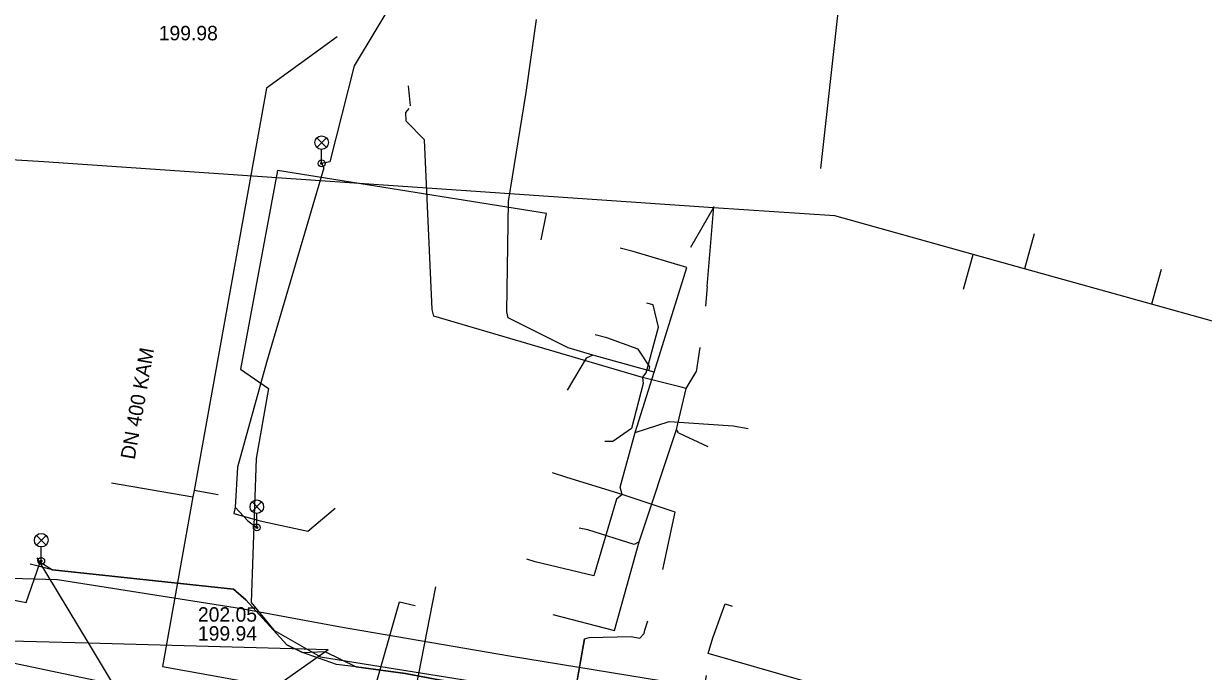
# Model space of a CAD drawing. Extents: x -596228 to -595156, y -1161235 to -1159373.
# Drawn here: x -596092 to -596026.7, y -1160278.1 to -1160242.3 of the extents above; entities that cross this region are included whole.
import ezdxf

# ---------------------------------------------------------------- set-up
doc = ezdxf.new("R2010")
doc.units = 0
for name, color, linetype in [('Vrstva 1', 7, 'Continuous'), ('Vrstva 12', 7, 'Continuous'), ('Vrstva 14', 7, 'Continuous'), ('Vrstva 16', 7, 'Continuous'), ('Vrstva 33', 7, 'Continuous'), ('Vrstva 4', 7, 'Continuous'), ('Vrstva 42', 7, 'Continuous'), ('Vrstva 5', 7, 'Continuous'), ('Vrstva 54', 7, 'Continuous'), ('Vrstva 55', 7, 'Continuous'), ('Vrstva 58', 7, 'Continuous'), ('Vrstva 9', 7, 'Continuous')]:
    doc.layers.add(name, color=color, linetype=linetype)

msp = doc.modelspace()

# ---------------------------------------------------------------- linework, layer by layer
at = {"layer": 'Vrstva 1'}
for p, q in [((-596046.34, -1160236.52), (-596047.88, -1160250.29)), ((-596074.64, -1160242.99), (-596078.56, -1160245.83)), ((-596070.71, -1160245.714), (-596070.6, -1160246.818)), ((-596069.388, -1160258.092), (-596069.806, -1160248.695)), ((-596055.054, -1160254.641), (-596053.794, -1160252.452)), ((-596054.16, -1160256.817), (-596053.787, -1160252.381)), ((-596036.053, -1160253.906), (-596036.589, -1160255.833)), ((-596039.967, -1160256.969), (-596039.431, -1160255.042)), ((-596029.011, -1160255.866), (-596029.547, -1160257.793)), ((-596054.16, -1160256.817), (-596054.245, -1160257.908)), ((-596069.278, -1160258.457), (-596069.388, -1160258.092)), ((-596057.143, -1160257.832), (-596057.484, -1160257.727)), ((-596056.838, -1160259.06), (-596057.143, -1160257.832)), ((-596057.527, -1160261.586), (-596056.838, -1160259.06)), ((-596054.564, -1160260.189), (-596054.765, -1160261.538)), ((-596057.725, -1160261.857), (-596057.527, -1160261.586)), ((-596055.31, -1160262.464), (-596054.765, -1160261.538)), ((-596055.853, -1160264.726), (-596055.31, -1160262.464)), ((-596055.31, -1160262.464), (-596055.59, -1160262.38)), ((-596058.349, -1160264.68), (-596059.382, -1160265.384)), ((-596057.912, -1160270.944), (-596055.853, -1160264.726)), ((-596055.747, -1160264.913), (-596055.853, -1160264.726)), ((-596059.382, -1160265.384), (-596059.827, -1160265.383)), ((-596055.747, -1160264.913), (-596054.118, -1160265.676)), ((-596087.13, -1160267.67), (-596082.629, -1160268.456)), ((-596081.22, -1160268.34), (-596082.566, -1160268.104))]:
    msp.add_line(p, q, dxfattribs=at)
for points in [[(-596078.56, -1160245.83), (-596082.566, -1160268.104), (-596082.629, -1160268.456), (-596084.32, -1160277.84)], [(-596069.806, -1160248.695), (-596070.817, -1160247.656), (-596070.835, -1160247.186), (-596070.655, -1160246.965)], [(-596090.88, -1160249.92), (-596130.326, -1160247.508), (-596132.717, -1160247.548), (-596135.072, -1160247.752)], [(-596047.09, -1160252.91), (-596053.794, -1160252.452), (-596090.88, -1160249.92)], [(-595998.91, -1160266.32), (-596008.526, -1160263.644), (-596008.747, -1160263.582), (-596020.751, -1160260.241), (-596029.547, -1160257.793), (-596036.589, -1160255.833), (-596039.431, -1160255.042), (-596047.09, -1160252.91)], [(-596055.59, -1160262.38), (-596057.725, -1160261.857), (-596069.278, -1160258.457)], [(-596057.725, -1160261.857), (-596057.694, -1160262.181), (-596058.349, -1160264.68)], [(-596062.702, -1160274.964), (-596059.291, -1160275.843), (-596057.912, -1160270.944), (-596058.189, -1160271.083), (-596060.762, -1160270.288), (-596061.249, -1160270.195)]]:
    msp.add_lwpolyline(points, dxfattribs=at)
at = {"layer": 'Vrstva 12'}
msp.add_line((-596053.16, -1160274.38), (-596052.77, -1160274.5), dxfattribs=at)
for points in [[(-596063.35, -1160254.23), (-596063.05, -1160252.78), (-596077.95, -1160250.4), (-596080, -1160261.38), (-596078.44, -1160262.45), (-596079.12, -1160266.34)], [(-596079.12, -1160266.34), (-596079.4, -1160274.31), (-596078.14, -1160275.84), (-596075.57, -1160277.3), (-596050.88, -1160281.26)], [(-596040.07, -1160283.09), (-596040.34, -1160282.25), (-596042.34, -1160281.47), (-596048.05, -1160278.86), (-596048.83, -1160278.64), (-596054.1, -1160277.12), (-596053.84, -1160276.26), (-596053.16, -1160274.38)]]:
    msp.add_lwpolyline(points, dxfattribs=at)
at = {"layer": 'Vrstva 14'}
for points in [[(-596073.176, -1160281.516), (-596073.112, -1160281.148), (-596073.04, -1160280.732), (-596071.197, -1160274.261), (-596070.32, -1160274.463)], [(-596080.37, -1160280.262), (-596080.665, -1160280.21), (-596082.606, -1160279.77), (-596095.596, -1160277.035), (-596097.65, -1160276.599), (-596104.647, -1160275.11), (-596105.055, -1160275.03), (-596105.65, -1160274.913)]]:
    msp.add_lwpolyline(points, dxfattribs=at)
at = {"layer": 'Vrstva 16'}
msp.add_lwpolyline([(-596073.52, -1160295.83), (-596073.39, -1160294.96), (-596069.19, -1160273.53), (-596069.17, -1160273.44)], dxfattribs=at)
at = {"layer": 'Vrstva 33'}
for p, q in [((-596075.765, -1160248.585), (-596075.235, -1160249.115)), ((-596075.765, -1160249.115), (-596075.235, -1160248.585)), ((-596075.5, -1160250), (-596075.5, -1160249.225)), ((-596079.355, -1160268.735), (-596078.825, -1160269.265)), ((-596079.355, -1160269.265), (-596078.825, -1160268.735)), ((-596079.09, -1160270.15), (-596079.09, -1160269.375)), ((-596091.291, -1160270.589), (-596090.761, -1160271.119)), ((-596091.291, -1160271.119), (-596090.761, -1160270.589)), ((-596091.026, -1160272.004), (-596091.026, -1160271.229))]:
    msp.add_line(p, q, dxfattribs=at)
for centre, radius in [((-596075.5, -1160248.85), 0.375), ((-596075.5, -1160250), 0.19), ((-596075.5, -1160250), 0.05), ((-596079.09, -1160269), 0.375), ((-596079.09, -1160270.15), 0.19), ((-596091.026, -1160270.854), 0.375), ((-596079.09, -1160270.15), 0.05), ((-596091.026, -1160272.004), 0.19), ((-596091.026, -1160272.004), 0.05)]:
    msp.add_circle(centre, radius, dxfattribs=at)
at = {"layer": 'Vrstva 42'}
msp.add_lwpolyline([(-596138.863, -1160251.371), (-596138.543, -1160251.731), (-596138.529, -1160252.118), (-596138.95, -1160254.63), (-596139.9, -1160258.88), (-596140.56, -1160262.64), (-596140.86, -1160263.55), (-596140.76, -1160264.3), (-596140.55, -1160264.76), (-596139.94, -1160265.17), (-596135.36, -1160266.41), (-596127.49, -1160267.65), (-596118.72, -1160268.94), (-596109.14, -1160270.6), (-596103.64, -1160272.23), (-596095.93, -1160272.87), (-596090.12, -1160273.02), (-596079.94, -1160274.63), (-596074.46, -1160275.64), (-596065.09, -1160277.26), (-596056.63, -1160278.63), (-596054.34, -1160279.2), (-596054.18, -1160278.35)], dxfattribs=at)
at = {"layer": 'Vrstva 5'}
for p, q in [((-596064.183, -1160246.083), (-596063.596, -1160242.034)), ((-596065.155, -1160252.104), (-596064.183, -1160246.083)), ((-596065.248, -1160258.209), (-596065.155, -1160252.104)), ((-596065.175, -1160258.556), (-596065.248, -1160258.209)), ((-596059.704, -1160259.651), (-596060.345, -1160259.491)), ((-596057.97, -1160260.272), (-596059.704, -1160259.651)), ((-596060.845, -1160260.787), (-596061.905, -1160262.549)), ((-596060.489, -1160260.606), (-596060.845, -1160260.787)), ((-596057.083, -1160261.559), (-596060.489, -1160260.606)), ((-596057.329, -1160261.252), (-596057.97, -1160260.272)), ((-596057.377, -1160261.477), (-596057.329, -1160261.252)), ((-596058.141, -1160264.895), (-596057.083, -1160261.559)), ((-596052.709, -1160264.522), (-596051.89, -1160264.676)), ((-596058.969, -1160267.924), (-596058.141, -1160264.895)), ((-596061.929, -1160267.377), (-596062.724, -1160267.129)), ((-596058.857, -1160268.325), (-596061.929, -1160267.377)), ((-596058.857, -1160268.325), (-596058.969, -1160267.924)), ((-596059.167, -1160268.581), (-596060.433, -1160272.827)), ((-596058.857, -1160268.325), (-596059.167, -1160268.581)), ((-596055.927, -1160269.298), (-596058.857, -1160268.325)), ((-596056.616, -1160272.475), (-596055.927, -1160269.298)), ((-596063.673, -1160272.055), (-596064.134, -1160271.896)), ((-596060.433, -1160272.827), (-596063.673, -1160272.055)), ((-596057.647, -1160276.023), (-596057.612, -1160275.834)), ((-596057.612, -1160275.834), (-596057.435, -1160275.309)), ((-596061.927, -1160281.895), (-596060.95, -1160276.32)), ((-596060.95, -1160276.32), (-596060.689, -1160276.232)), ((-596057.873, -1160276.282), (-596057.647, -1160276.023))]:
    msp.add_line(p, q, dxfattribs=at)
for points in [[(-596057.083, -1160261.559), (-596055.281, -1160255.755), (-596058.246, -1160254.881), (-596058.965, -1160254.687)], [(-596060.489, -1160260.606), (-596061.85, -1160260.21), (-596065.175, -1160258.556)], [(-596058.141, -1160264.895), (-596056.256, -1160264.292), (-596052.709, -1160264.522)], [(-596060.689, -1160276.232), (-596058.367, -1160276.191), (-596057.873, -1160276.282)]]:
    msp.add_lwpolyline(points, dxfattribs=at)
at = {"layer": 'Vrstva 54'}
for p, q in [((-596091.27, -1160271.82), (-596088.43, -1160276.54)), ((-596107.59, -1160276.02), (-596088.43, -1160276.54)), ((-596088.43, -1160276.54), (-596075.14, -1160276.9)), ((-596088.43, -1160276.54), (-596086.13, -1160280.35)), ((-596081.42, -1160281.31), (-596075.14, -1160276.9))]:
    msp.add_line(p, q, dxfattribs=at)
at = {"layer": 'Vrstva 55'}
for points in [[(-596070.05, -1160230.49), (-596070.45, -1160230.88), (-596069.61, -1160231.67), (-596068.48, -1160233.14), (-596070.1, -1160238.6), (-596073.7, -1160244.6), (-596075.039, -1160249.919), (-596075.5, -1160250), (-596075.38, -1160250.25), (-596078.55, -1160261.02), (-596080.15, -1160266.81), (-596080.28, -1160269.03), (-596079.58, -1160269.78), (-596079.09, -1160270.15)], [(-596228.22, -1160256.738), (-596220.191, -1160257.34), (-596205.22, -1160259.35), (-596195.13, -1160262), (-596168.709, -1160265.587), (-596168.17, -1160261.67), (-596155.903, -1160262.095), (-596136.72, -1160263.94), (-596136.82, -1160265.22), (-596091.86, -1160274.31), (-596091.109, -1160272.122), (-596091.02, -1160272.02)], [(-596080.28, -1160269.03), (-596080.37, -1160269.37), (-596078.9, -1160269.78), (-596076.26, -1160270.36), (-596074.75, -1160269.08)], [(-596091.02, -1160272.02), (-596091.04, -1160272.09), (-596090.4, -1160272.5), (-596080.38, -1160273.56), (-596079.69, -1160274.16), (-596077.43, -1160276.64), (-596076.56, -1160277.07), (-596075.32, -1160277.01), (-596073.59, -1160277.86), (-596070.87, -1160278.23), (-596069.21, -1160278.54), (-596055.92, -1160280.7), (-596055.718, -1160280.733), (-596055.673, -1160280.487), (-596055.59, -1160280.35), (-596055.555, -1160280.507), (-596055.596, -1160280.754), (-596046.89, -1160282.2), (-596041.48, -1160283.27), (-596024.848, -1160286.149)]]:
    msp.add_lwpolyline(points, dxfattribs=at)
at = {"layer": 'Vrstva 58'}
for points in [[(-596074.68, -1160277.74), (-596076.56, -1160277.07), (-596077.43, -1160276.64), (-596079.69, -1160274.16), (-596080.38, -1160273.56), (-596090.4, -1160272.5), (-596091.63, -1160272.18)], [(-595995.3, -1160291.92), (-595997.55, -1160291.41), (-595998.2, -1160290.64), (-595999.56, -1160290.39), (-596000.04, -1160290.82), (-596005.3, -1160289.88), (-596008.06, -1160289.45), (-596010.3, -1160289.07), (-596018.43, -1160287.47), (-596023.8, -1160286.33), (-596041.48, -1160283.27), (-596046.89, -1160282.2), (-596046.94, -1160282.19), (-596055.92, -1160280.7), (-596069.21, -1160278.54), (-596070.86, -1160278.23), (-596073.59, -1160277.86), (-596074.68, -1160277.74)]]:
    msp.add_lwpolyline(points, dxfattribs=at)
at = {"layer": 'Vrstva 9'}
for points in [[(-596060.95, -1160276.32), (-596061.62, -1160280.152), (-596061.924, -1160281.878)], [(-596084.32, -1160277.84), (-596061.924, -1160281.878), (-596036.79, -1160286.41)]]:
    msp.add_lwpolyline(points, dxfattribs=at)

# ---------------------------------------------------------------- texts
at = {"layer": 'Vrstva 12'}
for s, p in [('202.05', (-596082.349, -1160275.362)), ('199.94', (-596082.349, -1160276.412))]:
    msp.add_text(s, height=0.8, dxfattribs=at).set_placement(p)
at = {"layer": 'Vrstva 4'}
msp.add_text('199.98', height=0.8, dxfattribs=at).set_placement((-596084.52, -1160243.189))
msp.add_text('DN 400 KAM', height=0.8, rotation=80, dxfattribs=at).set_placement((-596085.854, -1160266.425))

doc.saveas('drawing.dxf')
